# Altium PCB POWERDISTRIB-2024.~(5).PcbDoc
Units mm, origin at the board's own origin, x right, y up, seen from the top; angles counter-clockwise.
Board outline 151.13 x 100.33 mm, 2 copper layers (Top Layer, Bottom Layer); 59 components, 25 nets, 145 pads, 64 vias.
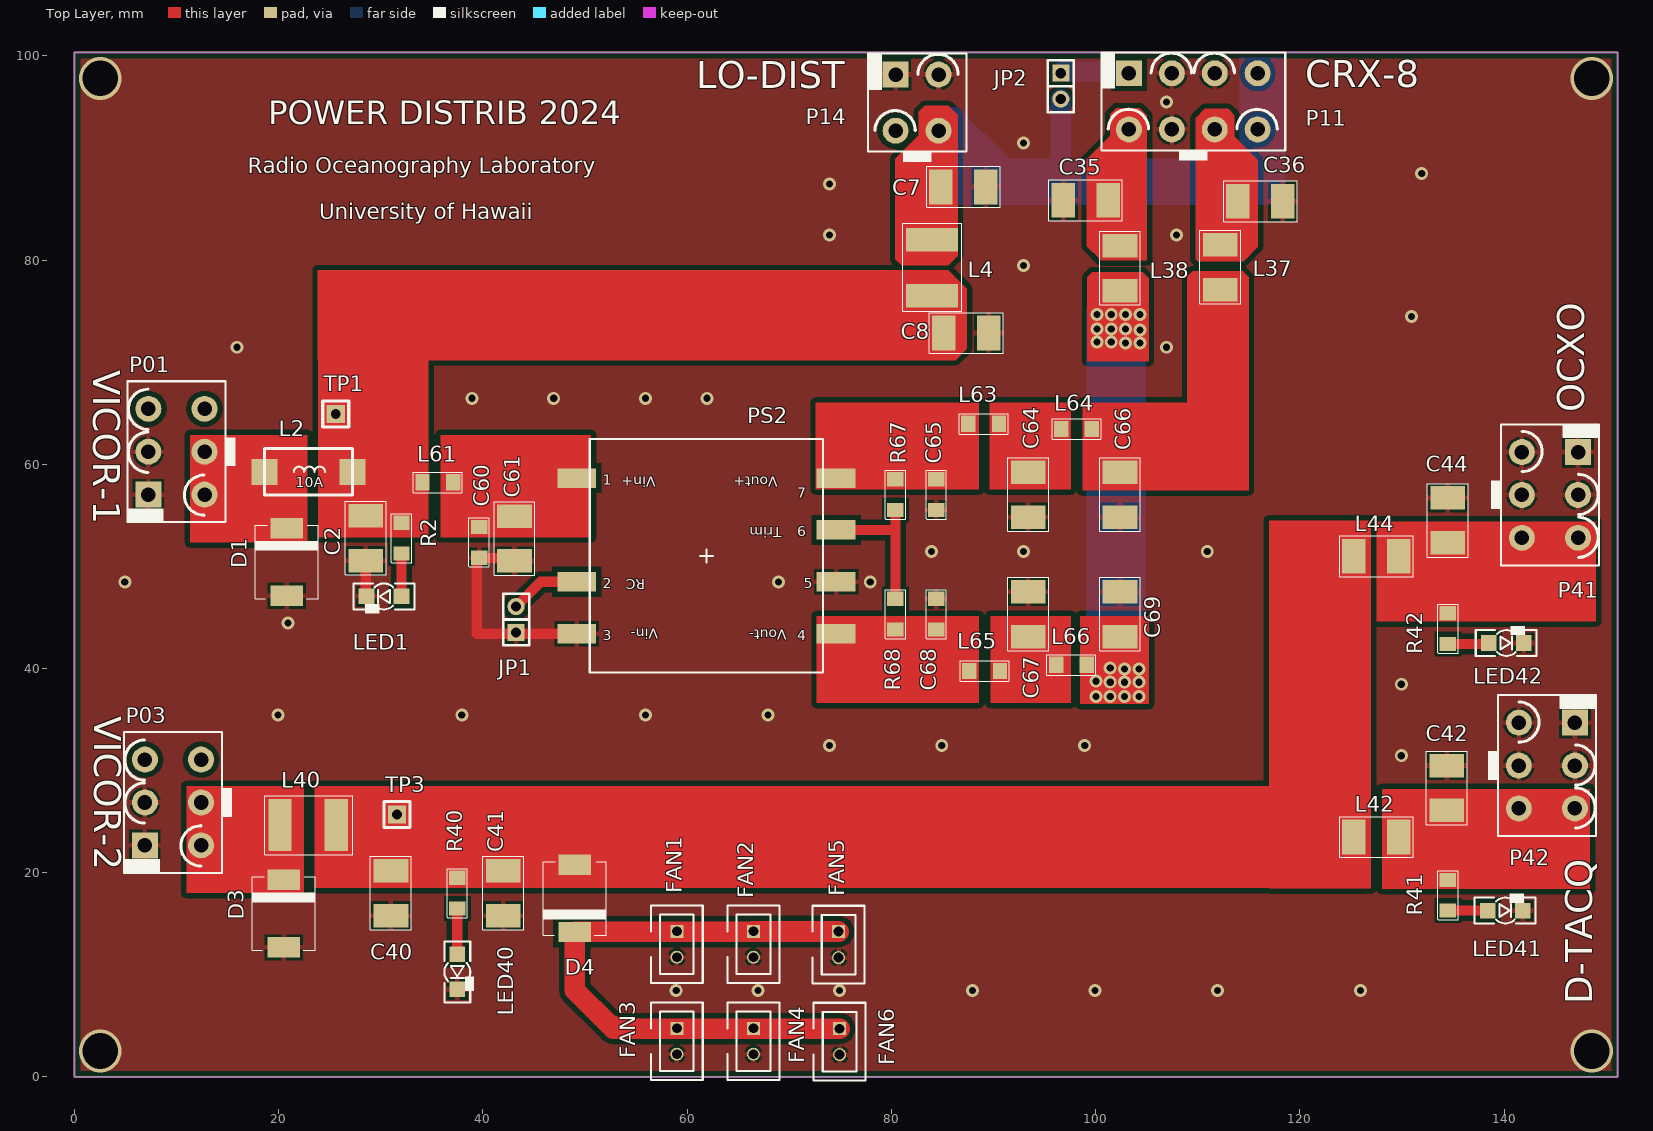
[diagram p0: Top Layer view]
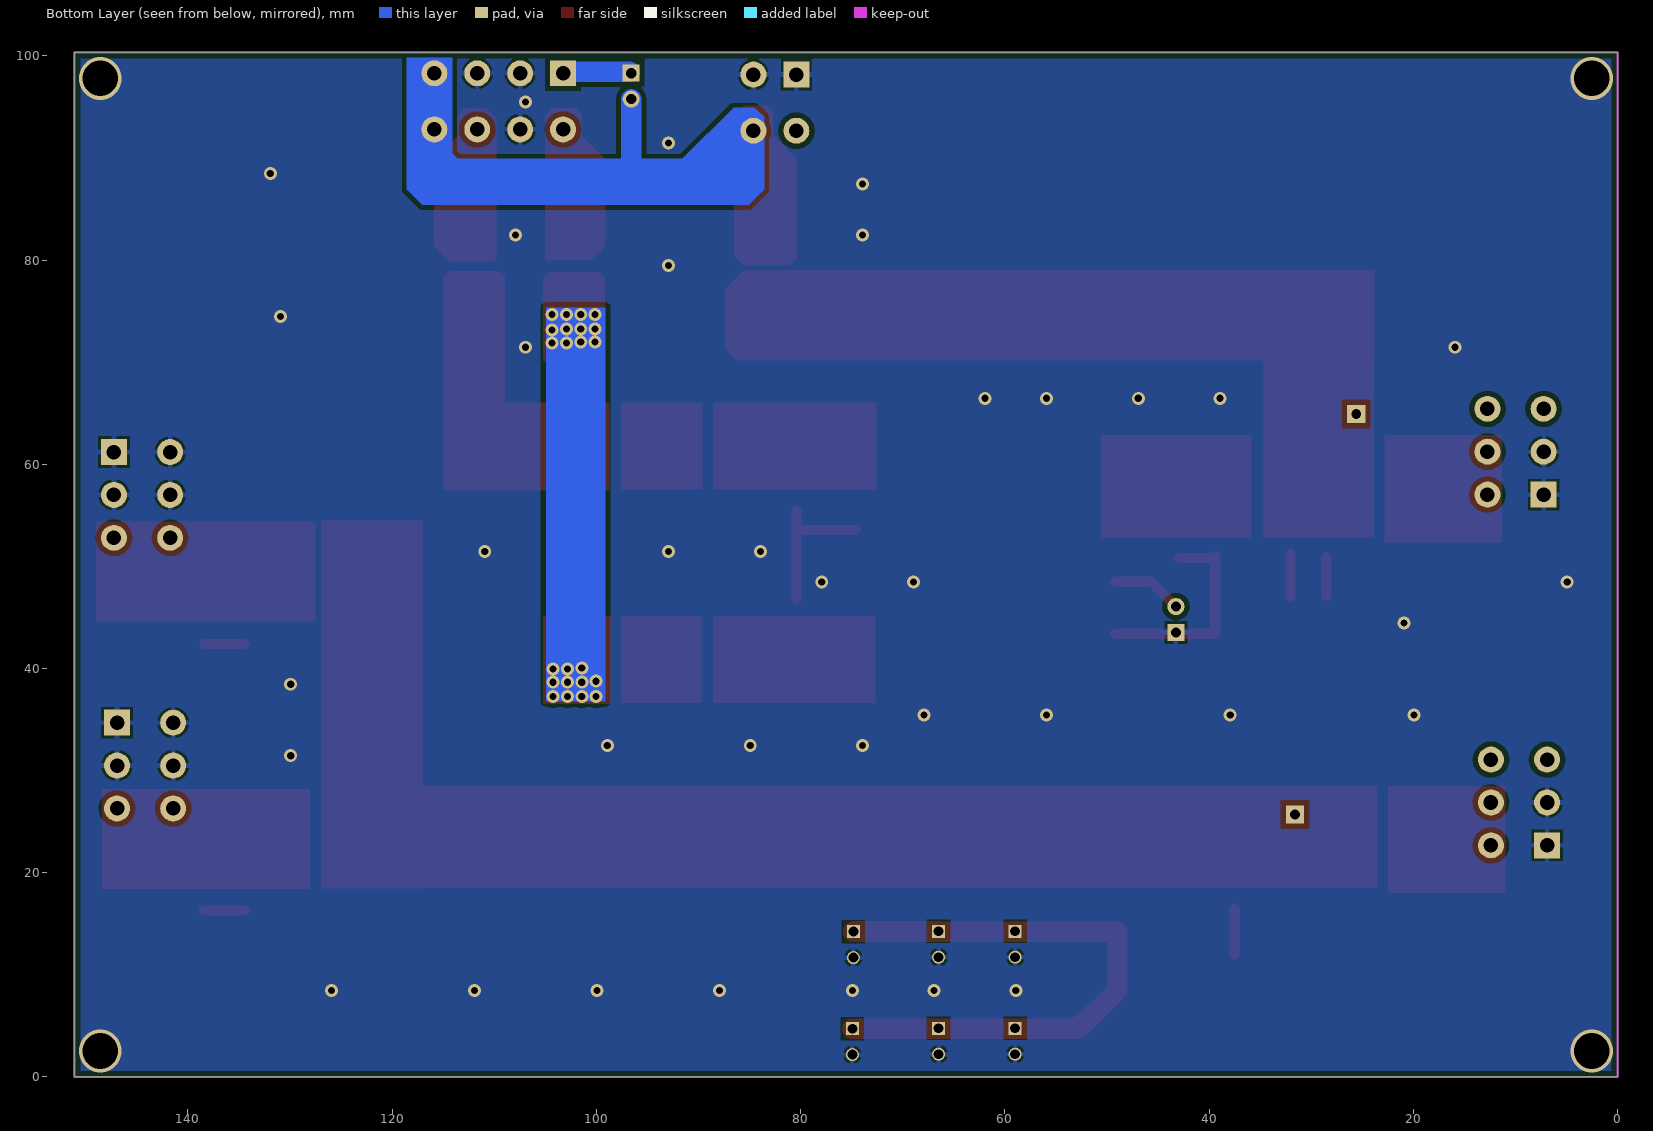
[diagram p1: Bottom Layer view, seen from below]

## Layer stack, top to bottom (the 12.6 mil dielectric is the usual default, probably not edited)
Top Solder: solder mask 0.0102, Solder Resist, Dk 3.5
Top Layer: signal copper 0.0356
Dielectric 1: dielectric 0.32, FR-4, Dk 4.8
Bottom Layer: signal copper 0.0356
Bottom Solder: solder mask 0.0102, Solder Resist, Dk 3.5

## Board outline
0,0 0,100.33 151.13,100.33 151.13,0

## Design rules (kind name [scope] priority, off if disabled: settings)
Clearance Clearance_1 [InPolygon] p1: gap=0.5 ignorepadtopadclearanceinfootprint=FALSE except(0: Arc-Hole Track-Hole SMDPad-Hole THPad-Hole Via-Hole Fill-Hole Poly-Hole Region-Hole Text-Hole)
Clearance [All] p2: gap=0.254 ignorepadtopadclearanceinfootprint=FALSE except(0: Arc-Hole Track-Hole SMDPad-Hole THPad-Hole Via-Hole Fill-Hole Poly-Hole Region-Hole Text-Hole)
ComponentClearance [All] p1 off: gap=0.254 collisioncheckmode=3 verticalgap=0.254 showdistances=FALSE
Height [All] p1 off: minheight=0 maxheight=25.4 prefheight=12.7
HoleSize [All] p1: absolutevalues=TRUE maxlimit=10 minlimit=0.025 maxpercent=80.000 minpercent=20.000
MinimumSolderMaskSliver [All] p1 off: minsoldermaskwidth=0.254
PolygonConnect [All] p1: thpad.connectstyle=Relief thpad.reliefconductorwidth=0.5 thpad.reliefentries=4 thpad.polygonreliefangle="90 Angle" thpad.airgapwidth=0.254 smdpad.connectstyle=Relief smdpad.reliefconductorwidth=0.5 smdpad.reliefentries=4 smdpad.polygonreliefangle="90 Angle" smdpad.airgapwidth=0.254 via.connectstyle=Direct via.reliefconductorwidth=0.5 via.reliefentries=4 via.polygonreliefangle="90 Angle" via.airgapwidth=0.254
RoomDefinition 2 [InComponentClass('2')] p1 off: confinementstyle=ConfineIn formatcopy=TRUE lockcomponents=FALSE outline -304.8,-305.1 -254,-305.1 -254,-279.7 -304.8,-279.7
RoomDefinition 1 [InComponentClass('1')] p2 off: confinementstyle=ConfineIn formatcopy=TRUE lockcomponents=FALSE outline -304.8,-305.1 -254,-305.1 -254,-279.7 -304.8,-279.7
RoutingVias [All] p1: holewidth=0.711 width=1.27 viastyle="Through Hole" minholewidth=0.711 minwidth=1.27 maxholewidth=3.5 maxwidth=8
SilkToSilkClearance [All] p1 off: silktosilkclearance=0.254
SilkToSolderMaskClearance [IsPad] p1 off: minsilkscreentomaskgap=0.254 clearancetoexposedcopper=TRUE
SolderMaskExpansion [All] p1: expansion=0.102 istentingtop=FALSE
Width [All] p1: maxlimit=15 minlimit=0.254 preferedwidth=1 minimp=50.000000 maximp=50.000000 favimp=50.000000
24 further rules are at their usual default settings.

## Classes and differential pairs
component class 1: C60 C61 C64 C65 C66 C67 C68 C69 JP1 L61 L63 L64 L65 L66 PS2 R67 R68
component class 2: C2 C7 C8 C35 C36 C40 C41 C42 C44 D1 D3 D4 FAN1 FAN2 FAN3 FAN4 FAN5 FAN6 JP2 L2 L4 L37 L38 L40 L42 L44 LED1 LED40 LED41 LED42 MH1 MH4 MH7 MH8 MH9 P01 P03 P11 P14 P41 P42 R2 R40 R41 R42 TP1 TP3

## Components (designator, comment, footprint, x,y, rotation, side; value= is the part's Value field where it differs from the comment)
C2 "22uF 25V" 1812 28.54,52.76 r270 top
C7 "22uF 25V" 1812 87.06,87.16 r0 top
C8 "4.7uF" 1812 87.34,72.86 r0 top
C35 "4.7uF" 1812 99.04,85.86 r180 top
C36 "4.7uF" 1812 116.14,85.76 r0 top
C40 "22uF 25V" 1812 31,18 r270 top
C41 "4.7uF" 1812 42,18 r270 top
C42 "22uF 25V" 1812 134.4,28.3 r90 top
C44 "22uF 25V" 1812 134.5,54.5 r90 top
C60 "100nF" 1206 39.64,52.36 r270 top
C61 "22uF 25V" 1812 43.1,52.73 r270 top
C64 "4.7uF" 1812 93.4,57.03 r270 top
C65 "100nF" 1206 84.4,57.03 r270 top
C66 "4.7uF" 1812 102.4,57.03 r270 top
C67 "4.7uF" 1812 93.4,45.33 r90 top
C68 "100nF" 1206 84.4,45.33 r270 top
C69 "4.7uF" 1812 102.4,45.33 r90 top
D1 "S5BC-13-F" SMC 20.8,50.43 r90 top
D3 "S5BC-13-F" SMC 20.5,16 r90 top
D4 "S5BC-13-F" SMC 49,17.5 r270 top
FAN1 "FAN1" SIP2-SHRD 59,13 r270 top
FAN2 "FAN2" SIP2-SHRD 66.5,13 r270 top
FAN3 "FAN3" SIP2-SHRD 59,3.5 r270 top
FAN4 "FAN4" SIP2-SHRD 66.5,3.5 r270 top
FAN5 "FAN1" SIP2-SHRD 74.84,12.96 r270 top
FAN6 "FAN2" SIP2-SHRD 74.94,3.46 r270 top
JP1 "" 2X2.54 43.26,43.53 r180 top
JP2 "" 2X2.54 96.6,98.3 r0 top
L2 "FER-10A" l3318 22.94,59.26 r0 top
L4 "FER-8A" 2220 84,79.3 r90 top
L37 "220uH" 1812 112.2,79.3 r90 top
L38 "220uH" 1812 102.4,79.2 r90 top
L40 "FER-8A" 2220 22.94,24.66 r0 top
L42 "FER-3A" 1812 127.5,23.5 r0 top
L44 "FER-3A" 1812 127.5,51 r0 top
L61 "Ferrite" 1206 35.6,58.23 r0 top
L63 "Ferrite" 1206 89.04,63.96 r0 top
L64 "Ferrite" 1206 98.14,63.46 r0 top
L65 "Ferrite" 1206 89.14,39.76 r0 top
L66 "Ferrite" 1206 97.64,40.36 r0 top
LED1 "12V BUS" LED1206 32.04,47.06 r180 top
LED40 "+5V" LED1206 37.5,12 r270 top
LED41 "D-tAcq" LED1206 138.4,16.3 r0 top
LED42 "OSC" LED1206 138.5,42.5 r0 top
P01 "12V" MFTJR2X3 10,61.23 r90 top
P03 "13.5V" MFTJR2X3 9.66,26.88 r90 top
P11 "RX POWER" MFTJR2X4 109.575,95.539 r0 top
P14 "LO SPLIT" MFTJR2X2 82.526,95.411 r0 top
P41 "D-tAcq" MFTJR2X3 144.5,57 r270 top
P42 "OSCILLATOR" MFTJR2X3 144.2,30.5 r270 top
PS2 "CC6-1212DR-E" DCDC-CC6/B 61.9,51.03 r0 top
R2 "4.99K" 1206 32.04,52.76 r270 top
R40 "4.99K" 1206 37.5,18 r270 top
R41 "4.99K" 1206 134.5,17.8 r270 top
R42 "4.99K" 1206 134.5,43.9 r270 top
R67 "Rdown" 1206 80.4,57.03 r270 top
R68 "Rup" 1206 80.4,45.33 r270 top
TP1 "+12V" TP 25.6,64.93 r0 top
TP3 "+13.5V" TP 31.6,25.7 r0 top

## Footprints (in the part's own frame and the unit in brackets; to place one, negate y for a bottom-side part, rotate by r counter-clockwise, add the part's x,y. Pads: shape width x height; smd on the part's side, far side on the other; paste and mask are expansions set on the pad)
2X2.54 [mm]
  rect 1.67x1.67 hole 1: 1(0,0)
  round 1.67 hole 1: 2(0,-2.54)
  silkscreen extent -1.27,-3.81 1.27,1.27, body extent -1.26,-3.8 1.28,1.28, height 9.54
1206 [mm]
  rect 1.4x1.6 smd mask+0.05: 1(-1.5,0) 2(1.5,0)
  silkscreen extent -2.4,-1 2.4,1, body extent -1.6,-0.8 1.6,0.8, height 1
1812 [mm]
  rect 2.3x3.4 smd: 1(-2.2,0) 2(2.2,0)
  silkscreen extent -3.6,-2 3.6,2, body extent -2.25,-1.6 2.25,1.6, height 1.6
2220 [mm]
  rect 2.3x5.1 smd: 1(-2.8,0) 2(2.7,0)
  silkscreen extent -4.3,-2.9 4.3,2.9, body extent -2.86,-2.53 2.84,2.47, height 2.3
DCDC-CC6/B [mm]
  rect 3.81x1.905 smd: 1(-12.7,7.62) 2(-12.7,-2.54) 3(-12.7,-7.62) 4(12.7,-7.62) 5(12.7,-2.54) 6(12.7,2.54) 7(12.7,7.62)
  silkscreen extent -11.43,-11.43 11.43,11.43, body extent -13.08,-10.55 13.08,10.55, height 8.8
l3318 [mil]
  rect 100x100 smd: 1(-170,0) 2(170,0)
  silkscreen extent -170,-90 170,90
LED1206 [mil]
  rect 60x60 smd: 1(0,0) 2(135,0)
  silkscreen extent -50,-50 185,65
MFTJR2X2 [mm]
  rect 2.54x2.54 hole 1.422: 1(-2.1,2.75)
  round 2.54 hole 1.422: 2(2.1,2.75) 3(-2.1,-2.75) 4(2.1,-2.75)
  silkscreen extent -4.85,-5.8 4.85,4.85, body extent -5.2,-6.07 5.2,4.93, height 12.8
MFTJR2X3 [mm]
  rect 2.54x2.54 hole 1.422: 1(-4.2,2.75)
  round 2.54 hole 1.422: 2(0,2.75) 3(4.2,2.75) 4(-4.2,-2.75) 5(0,-2.75) 6(4.2,-2.75)
  silkscreen extent -6.95,-5.79 6.9,4.85, body extent -7.3,-5.92 7.3,5.08, height 12.8
MFTJR2X4 [mm]
  rect 2.54x2.54 hole 1.422: 1(-6.3,2.75)
  round 2.54 hole 1.422: 2(-2.1,2.75) 3(2.1,2.75) 4(6.3,2.75) 5(-6.3,-2.75) 6(-2.1,-2.75) 7(2.1,-2.75) 8(6.3,-2.75)
  silkscreen extent -9.05,-5.8 9,4.85, body extent -9.4,-6.2 9.4,4.8, height 12.8
SIP2-SHRD [mil]
  rect 50x50 hole 38: 1(-50,0)
  round 50 hole 38: 2(50,0)
  silkscreen extent -150,-100 150,100
SMC [mm]
  rect 2x3.2 smd: A(-3.304,0) K(3.304,0)
  silkscreen extent -3.6,-3.1 3.6,3.1, body extent -4.05,-3.13 4.08,3.17, height 2.62
TP [mil]
  rect 70x70 hole 38: TP(0,0)
  silkscreen extent -50,-50 50,50

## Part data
C2 C7 C42 C44 C61 C64 C66 C67 C68 C69: library part C1206
C8 C35 C36 C41: library part CAP1206
C40: library part "CAPACITOR POL"
C60 C65: library part CAP_SHORT
D1 D3 D4: library part DIODE2
FAN1 FAN2 FAN3 FAN4 FAN5 FAN6: library part "HEADER 2_0"
JP1 JP2: library part STRAP
L2 L4 L40: library part FERRITE1812_0
L37 L38 L61 L63 L64 L65 L66: library part INDUCTOR
L42 L44: library part FERRITE_0
LED1: library part LED_1
LED40 LED41 LED42: library part LED_0
P01 P03 P41 P42: library part "HEADER 3X2_0"
P11: library part "HEADER 4X2_0"
P14: library part "HEADER 2X2_5"
PS2: library part "CONV +-15V_1"
R2 R40 R41 R42: library part RES1206
R67 R68: library part R1206
TP1 TP3: library part TP

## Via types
v1: diameter 1.27, hole 0.7, Top Layer to Bottom Layer, 60 vias
v2: diameter 4.2, hole 3.5, Top Layer to Bottom Layer, 4 vias

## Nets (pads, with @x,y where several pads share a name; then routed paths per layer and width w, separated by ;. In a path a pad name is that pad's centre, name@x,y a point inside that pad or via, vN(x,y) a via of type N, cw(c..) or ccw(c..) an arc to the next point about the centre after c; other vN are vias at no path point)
12VA1: C2.1 C8.1 L2.2 L4.1 L61.1 R2.1 TP1.TP | length 3.5
  Top Layer w1: 25.6,61.83 25.9,61.53
  Top Layer w2: 25.6,61.83 TP1.TP
12VA2: C60.1 C61.1 L61.2 PS2.1
FANS: D4.K FAN1.1 FAN2.1 FAN3.1 FAN4.1 FAN5.1 FAN6.1 | length 67.2
  Top Layer w2: 52.77,4.73 FAN6.1 ; 52.77,5 52.5,5 49,8.5 D4.K 49.034,14.23 FAN5.1 ; FAN2.1 FAN5.1@74.8,14.27
GND: C2.2 C7.2 C8.2 C35.2 C36.2 C40.2 C41.2 C42.2 C44.2 C60.2 C61.2 C64.2 C65.2 C66.2 C67.2 C68.1 C69.2 D1.A D3.A FAN1.2 FAN2.2 FAN3.2 FAN4.2 FAN5.2 FAN6.2 JP1.1 LED1.2 LED40.2 LED41.2 LED42.2 P01.1 P01.2 P03.1 P03.2 P11.2 P11.3 P11.6 P14.1 P14.2 P41.1 P41.2 P41.4 P41.5 P42.1 P42.2 P42.4 P42.5 PS2.3 PS2.5 | length 24.9
  Top Layer w1: LED1.2@28.54,47.131 C2.2@28.54,50.89 ; 39.4,43.43 39.4,51.03 39.5,50.83 C61.2@43,50.83 ; 39.42,43.41 PS2.3
  other v1: 58.94,8.46 66.94,8.46 74.94,8.46 87.94,8.46 99.94,8.46 111.94,8.46 125.94,8.46 129.94,31.46 73.94,32.46 84.94,32.46 98.94,32.46 19.94,35.46 37.94,35.46 55.94,35.46 67.94,35.46 129.94,38.46 20.94,44.46 4.94,48.46 68.94,48.46 77.94,48.46 83.94,51.46 92.94,51.46 110.94,51.46 38.94,66.46 46.94,66.46 55.94,66.46 61.94,66.46 15.94,71.46 106.94,71.46 130.94,74.46 92.94,79.46 73.94,82.46 107.94,82.46 73.94,87.46 131.94,88.46 92.94,91.46 106.94,95.46
  other v2: 2.54,2.54 148.59,2.54 2.54,97.79 148.59,97.79
NetC42_1: C42.1 L42.2 P42.3 P42.6 R41.1
NetD3_K: D3.K L40.1 P03.4 P03.5
NetJP1_2: JP1.2 PS2.2 | length 6.9
  Top Layer w1: JP1.2 45.68,48.49 PS2.2
NetLED1_1: LED1.1 R2.2 | length 4.2
  Top Layer w1: LED1.1 R2.2
NetLED40_1: LED40.1 R40.2 | length 4.5
  Top Layer w1: LED40.1 R40.2
NetLED41_1: LED41.1 R41.2 | length 3.9
  Top Layer w1: R41.2 LED41.1
NetLED42_1: LED42.1 R42.2 | length 3.9
  Top Layer w1: R42.2 LED42.1@138.4,42.4
NetPS2_6: PS2.6 R67.2 R68.1 | length 14.6
  Top Layer w1: PS2.6 80.16,53.57 80.4,53.33 ; R68.1 80.4,53.33 ; R67.2 80.4,53.33
PANT1: JP2.1 P11.1 | length 6.6
  Bottom Layer w2: JP2.1@96.75,98.45 P11.1@103.3,98.45
V12IN1: D1.K L2.1 P01.4 P01.5
V12REC3: C7.1 JP2.2 L4.2 P11.4 P11.8 P14.4 | length 7.5
  Bottom Layer w2: 96.6,88.3 JP2.2
V13OUT4: C40.1 C41.1 D4.A L40.2 L42.1 L44.1 R40.1 TP3.TP
V13OUT9: C44.1 L44.2 P41.3 P41.6 R42.1
VCC1: C65.1 L63.1 PS2.7 R67.1
VCC2: C64.1 L63.2 L64.1
VCC3: C66.1 L37.1 L64.2
VCC5: C36.1 L37.2 P11.7
VEE1: C68.2 L65.1 PS2.4 R68.2
VEE2: C67.1 L65.2 L66.1
VEE3: C69.1 L38.1 L66.2
  other v1: 100.04,37.26 101.44,37.26 102.84,37.26 104.24,37.26 101.44,38.66 102.84,38.66 104.24,38.66 100.04,38.76 102.84,39.96 104.24,39.96 101.44,40.06 102.94,71.86 104.34,71.86 100.14,71.96 101.54,71.96 104.34,73.16 100.14,73.26 101.54,73.26 102.94,73.26 100.14,74.66 101.54,74.66 102.94,74.66 104.34,74.66
VEE5: C35.1 L38.2 P11.5
pads on no net: P01.3 P01.6 P03.3 P03.6 P14.3

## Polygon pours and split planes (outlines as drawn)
GND on Bottom Layer "Bottom Layer-No Net" (solid, remove dead copper, pour order 0): -1.5,-1.5 154,-1.5 154,103.5 -2,103.5
GND on Top Layer "Bottom Layer-No Net" (solid, remove dead copper, pour order 2): -1.5,-1.5 154,-1.5 154,103.5 -2,103.5

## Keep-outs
Keep-Out Layer:
  the board outline again, w0.2

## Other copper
Top Layer:
  region net VEE3: 105.24,45.13 98.5,45.13 98.5,36.53 105.24,36.53
  region net VEE2: 97.6,45.13 89.7,45.13 89.7,36.63 97.6,36.63
  region net VEE1: 88.6,45.13 72.7,45.13 72.7,36.63 88.6,36.63
  region net VCC3: 114.84,66.03 98.7,66.03 98.7,57.43 114.84,57.43
  region net VCC2: 97.6,66.03 89.6,66.03 89.6,57.53 97.6,57.53
  region net VCC1: 88.6,66.03 72.6,66.03 72.6,57.53 88.6,57.53
  region net 12VA2: 50.6,62.85 35.84,62.85 35.84,52.85 50.6,52.85
  region net 12VA1: 34.7,71.96 23.84,71.96 23.84,52.85 34.7,52.85
  region net V12IN1: 22.84,62.85 11.34,62.85 11.34,52.35 22.84,52.35
  region net NetC42_1: 148.429,28.195 128.029,28.195 128.029,18.395 148.429,18.395
  region net V13OUT9: 149,54.4 127.5,54.4 127.5,44.6 149,44.6
  region net NetD3_K: 22.5,28.5 11,28.5 11,18 22.5,18
  region net V13OUT4: 125,28.5 23.5,28.5 23.5,18.5 125,18.5
  region net V13OUT4: 127,54.5 117,54.5 117,18.46 127,18.46
  region net VCC3: 109,78.4 109.5,78.9 114.4,78.9 115,78.3 115,57.46 109,57.46
  region net VEE3: 99.2,78.3 99.7,78.8 104.6,78.8 105.2,78.2 105.2,70.1 99.2,70.1
  region net 12VA1: 85.6,79 87.4,77.2 87.4,71.3 86.3,70.2 23.84,70.2 23.84,79
  region net V12REC3: 85.6,95.1 86.5,94.2 86.5,80.4 85.6,79.5 81,79.5 80.4,80.1 80.4,89.9 82.7,92.2 82.7,94.5 83.3,95.1
  region net VEE5: 104.34,94.86 105.04,94.16 105.04,79.96 100.54,79.96 99.14,81.36 99.14,89.86 99.64,90.36 101.44,92.16 101.44,94.26 102.04,94.86
  region net VCC5: 110.7,94.8 109.8,93.9 109.8,80.1 110,79.9 114.5,79.9 115.9,81.3 115.9,89.8 115.4,90.3 113.6,92.1 113.6,94.2 113,94.8
Bottom Layer:
  region net VEE3: 104.94,75.36 99.14,75.36 99.14,36.76 104.94,36.76
  region net V12REC3: 84.19,94.637 83.579,94.025 83.579,86.908 85.079,85.408 117.079,85.408 118.579,86.908 118.579,99.815 114.121,99.815 114.121,90.45 113.579,89.908 91.579,89.908 86.579,94.908 84.579,94.908

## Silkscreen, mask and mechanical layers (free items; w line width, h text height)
Top Overlay:
  text "CRX-8" at 120.559,96.016 h4.5
  text "LO-DIST" at 60.89,95.924 h4.5
  text "POWER DISTRIB 2024" at 19,92.5 h4
  text "Radio Oceanography Laboratory" at 17,88.5 h1.52
  text "University of Hawaii" at 24,84 h1.52
  text "VICOR-1" at 0.978,69.209 h4.5 r270
  text "OCXO" at 148.718,65.087 h4.5 r90
  text "VICOR-2" at 1.088,35.334 h4.5 r270
  text "D-TACQ" at 149.506,7.108 h4.5 r90
Mechanical 5:
  lines w0.127: 78.643,-91.59 78.643,-82.909 ; 117.751,-76.084 235.054,-76.084 ; 117.751,-69.259 235.054,-69.259 ; 117.751,-58.169 235.054,-58.169 ; 117.751,-53.903 235.054,-53.903 ; 117.751,-49.637 235.054,-49.637 ; 117.751,-45.372 235.054,-45.372 ; 141.126,-62.434 141.126,-41.106 ; 158.624,-82.909 158.624,-62.434 ; 198.822,-62.434 198.822,-41.106 ; 217.845,-62.434 217.845,-41.106 ; 235.054,-41.106 78.643,-41.106 ; 78.643,-82.909 78.643,-41.106 ; 78.643,-82.909 117.751,-82.909 ; 78.643,-82.909 235.054,-82.909 ; 78.643,-41.106 117.751,-41.106 ; 117.751,-82.909 117.751,-62.434 ; 117.751,-82.909 235.054,-82.909 ; 117.751,-82.909 117.751,-41.106 ; 117.751,-82.909 117.751,-41.106 ; 117.751,-62.434 235.054,-62.434 ; 117.751,-62.434 235.054,-62.434 ; 216.986,-82.909 216.986,-69.259 ; 216.986,-82.909 235.054,-82.909 ; 216.986,-82.909 216.986,-69.259 ; 216.986,-76.084 216.986,-69.259 ; 216.986,-76.084 235.054,-76.084 ; 216.986,-76.084 216.986,-69.259 ; 216.986,-69.259 235.054,-69.259 ; 216.986,-69.259 235.054,-69.259 ; 235.054,-82.909 235.054,-62.434 ; 235.054,-82.909 235.054,-69.259 ; 235.054,-76.084 235.054,-69.259
  lines w0.5: -39.239,118.422 235.063,118.422 235.063,-91.578 78.663,-91.578 -38.937,-91.578 ; -38.937,-91.517 -38.937,118.963
  text "Radio / Oceanography / Laboratory" at 84.59,-55.696 h4
  text "Indice" at 121.812,-61.025 h1.76
  text "Modification" at 160.781,-61.025 h1.76
  text "Date" at 204.455,-61.025 h1.76
  text "Dessine par" at 220.01,-61.107 h1.5
  text "Edition" at 118.722,-67.036 h1.76
  text ":" at 138.66,-67.036 h1.76
  text "CARTE POWER-DISTRIB-2024" at 162.463,-67.678 h1.8
  text "Dessinateur" at 118.722,-73.047 h1.76
  text "Folio" at 217.861,-73.047 h1.8
  text ":" at 138.66,-73.068 h1.76
  text ":" at 226.33,-73.068 h1.76
  text "1/1" at 228.707,-73.444 h1.76
  text "RONVEL" at 141.728,-73.559 h1.95
  text ":" at 138.66,-79.661 h1.76
  text "Date" at 118.722,-79.712 h1.76
  text "Ind" at 217.861,-79.712 h1.95
  text "15/11/24" at 140.613,-80.828 h1.8
Mechanical 7:
  text "PLAN DE CABLAGE" at 166.463,-74.178 h4
Mechanical 9:
  text "PLAN DE PERCAGE" at 172.063,-74.078 h4
Drill Drawing:
  circle w0.1: c-28.834,-31.549 r0.772
  lines w0.1: -30.95,-36.839 68.345,-36.839 ; -30.95,-19.464 68.345,-19.464 ; -18.61,-40.314 -18.61,-15.989 ; -5.44,-40.314 -5.44,-15.989 ; 20.93,-40.314 20.93,-15.989 ; 32.228,-40.314 32.228,-15.989 ; 48.806,-40.314 48.806,-15.989 ; -30.95,-40.314 68.345,-40.314 68.345,-15.989 -30.95,-15.989 -30.95,-40.314 ; -29.606,-35.796 -28.062,-35.796 -28.062,-34.252 -29.606,-34.252 -29.606,-35.796 ; -29.606,-27.302 -28.062,-27.302 -28.834,-28.846 -29.606,-27.302 ; -29.606,-24.985 -29.22,-24.985 -29.22,-25.371 -28.448,-25.371 -28.448,-24.985 -28.062,-24.985 -28.062,-24.213 -28.448,-24.213 -28.448,-23.827 -29.22,-23.827 -29.22,-24.213 -29.606,-24.213 -29.606,-24.985 ; -29.606,-21.896 -28.834,-21.51 -28.062,-21.896 -28.448,-21.124 -28.062,-20.352 -28.834,-20.738 -29.606,-20.352 -29.22,-21.124 -29.606,-21.896
  text "Symbol" at -28.865,-18.421 h1.67
  text "Count" at -17.567,-18.421 h1.67
  text "Hole Size" at -4.397,-18.421 h1.67
  text "Plated" at 21.973,-18.421 h1.67
  text "Hole Type" at 33.271,-18.421 h1.67
  text "Technology" at 49.849,-18.421 h1.67
  text "4" at -17.567,-21.896 h1.39
  text "1.000mm (39.37mil)" at -4.397,-21.896 h1.39
  text "PTH" at 21.973,-21.896 h1.39
  text "Round" at 33.271,-21.896 h1.39
  text "(Mixed)" at 49.849,-21.896 h1.39
  text "4" at -17.567,-25.371 h1.39
  text "3.500mm (137.79mil)" at -4.397,-25.371 h1.39
  text "PTH" at 21.973,-25.371 h1.39
  text "Round" at 33.271,-25.371 h1.39
  text "v420h350m430" at 49.849,-25.371 h1.39
  text "14" at -17.567,-28.846 h1.39
  text "0.965mm (38.00mil)" at -4.397,-28.846 h1.39
  text "PTH" at 21.973,-28.846 h1.39
  text "Round" at 33.271,-28.846 h1.39
  text "(Mixed)" at 49.849,-28.846 h1.39
  text "36" at -17.567,-32.321 h1.39
  text "1.422mm (56.00mil)" at -4.397,-32.321 h1.39
  text "PTH" at 21.973,-32.321 h1.39
  text "Round" at 33.271,-32.321 h1.39
  text "(Mixed)" at 49.849,-32.321 h1.39
  text "60" at -17.567,-35.796 h1.39
  text "0.700mm (27.56mil)" at -4.397,-35.796 h1.39
  text "PTH" at 21.973,-35.796 h1.39
  text "Round" at 33.271,-35.796 h1.39
  text "v127h70m64" at 49.849,-35.796 h1.39
  text "118 Total" at -17.567,-39.271 h1.39
  text "Matiere FR4 16/10eme / TECHNO 2 COUCHES / Cuivre 35 microns 2 faces / Vernis selectif vert 2 faces / Serigraphie blanche 2 faces / Finition NiAu" at -32,-76.5 h3

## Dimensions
0,0 to 151.13,0 on Drill Drawing
2.54,2.54 to 0,0 on Drill Drawing
2.54,2.54 to 148.59,2.54 on Drill Drawing
2.54,2.54 to 2.54,97.79 on Drill Drawing
0,100.33 to 0,0 on Drill Drawing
